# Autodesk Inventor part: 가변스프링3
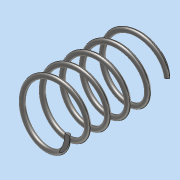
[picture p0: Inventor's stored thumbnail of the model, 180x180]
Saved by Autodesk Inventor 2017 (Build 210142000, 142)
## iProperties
Part Number: 가변스프링3
Material: 강철, 연강
Document SubType Name: Modeling
Designer: MRC
Density: 7.85 g/cm^3
Appearance: 반연마
Mass: 8.43463 g
Surface Area: 21.7444 cm^2
Volume: 1.07448 cm^3
Author: MRC
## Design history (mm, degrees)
sketch "스케치1"
  geometry: L1 (0, 0)-(0, -40.108); L2 (0, 0)-(11, 0); L3 (0, -40.108)-(11.069, -40.108); C1 r 1 at (11, 0)
  constraints: 6 end point, 2 horizontal, 1 centre point, 1 coincident, 1 vertical
  dimensions: "d1" = 22 diameter of L2.end L1; "d2" = 2 diameter of C1; "d4" = 40.10829 distance of L1.start L1.end (derived)
feature "코일1" sketch "스케치1" pitch "d5" = 10; turns "d7" = 5; dims "d6" = 40.10829 (= d4), "d8" = 0, angle "d9" = 90 deg, angle "d10" = 90 deg, "d11" = 0, "d12" = 0
sketch "스케치2"
  geometry: L1 (0, 21.213)-(-40.108, 21.213); L2 (-40.108, 21.213)-(-40.108, -18.04); L3 (-40.108, -18.04)-(0, -18.04); L4 (0, -18.04)-(0, 21.213); 1 further point
  constraints: 8 end point, 2 parallel, 1 horizontal, 1 perpendicular, 1 point on line
  dimensions: "d17" = 40.10829 distance of L2.end L3.end (= d4)
extrude "돌출1" sketch "스케치2" stored distance "d15" = 30; taper "d16" = 0 deg
node "솔리드1"
